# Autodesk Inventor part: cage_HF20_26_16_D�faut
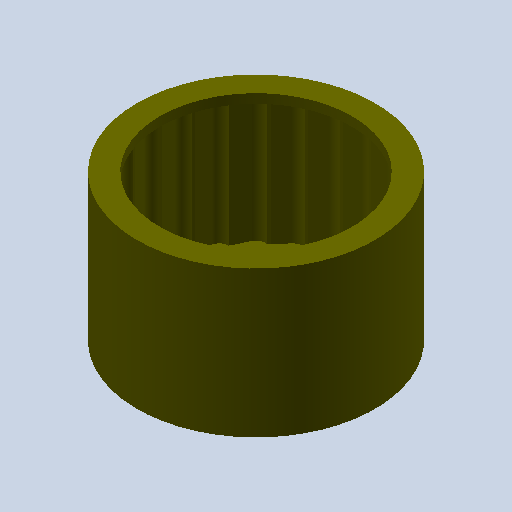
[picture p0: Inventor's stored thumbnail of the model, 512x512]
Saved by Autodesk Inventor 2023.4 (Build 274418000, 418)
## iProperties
Created: 2011-01
Part Number: cage_HF20_26_16_D�faut
Document SubType Name: Modeling
Designer: eric
Density: 1 g/cm^3
Mass: 1.73301 g
Surface Area: 30.9074 cm^2
Volume: 1.73301 cm^3
Material: Générique
Appearance: 128,128,0_1
Author: eric
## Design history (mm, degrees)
feature "Base1"
node "Corps solides"
node "Corps surfaciques"
node "Solide1"
